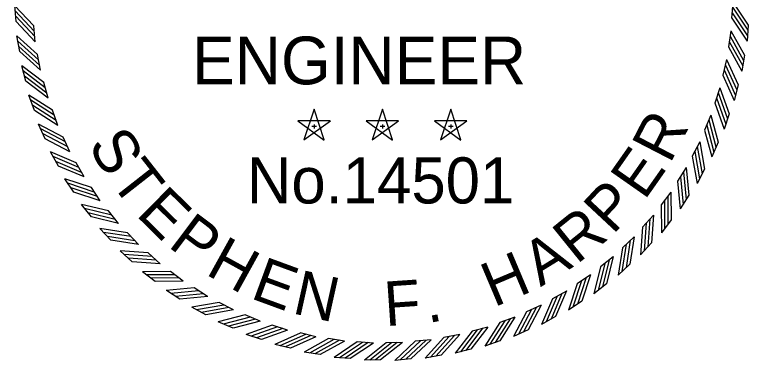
# Model space of a CAD drawing. Extents: x -129 to 14744569, y -102 to 1829048.
# Drawn here: x -104.853 to -102.792, y -100.653 to -99.681 of the extents above; entities that cross this region are included whole.
import ezdxf

# ---------------------------------------------------------------- set-up
doc = ezdxf.new("R2010")
doc.units = 0
doc.layers.add('STAMP', color=7, linetype='Continuous')

msp = doc.modelspace()

# ---------------------------------------------------------------- linework, layer by layer
at = {"layer": 'STAMP'}
for p, q in [((-104.8484, -99.6998), (-104.8525, -99.6547)), ((-102.8353, -99.6452), (-102.8387, -99.6904)), ((-104.7948, -99.7568), (-104.7989, -99.7117)), ((-102.7919, -99.7103), (-102.7952, -99.7554)), ((-102.8408, -99.7264), (-102.8478, -99.7712)), ((-104.8383, -99.7845), (-104.8461, -99.7399)), ((-104.7801, -99.8369), (-104.788, -99.7922)), ((-102.8028, -99.7948), (-102.8099, -99.8395)), ((-102.8529, -99.8068), (-102.8637, -99.8509)), ((-104.8212, -99.868), (-104.8327, -99.8243)), ((-104.7589, -99.9155), (-104.7705, -99.8716)), ((-102.8208, -99.8782), (-102.8315, -99.9222)), ((-102.8717, -99.886), (-102.886, -99.9291)), ((-104.7973, -99.9499), (-104.8124, -99.9072)), ((-104.7313, -99.992), (-104.7464, -99.9493)), ((-104.0117, -99.9462), (-104.04, -100.033)), ((-103.9835, -100.033), (-104.0116, -99.9461)), ((-103.8198, -99.9462), (-103.8481, -100.033)), ((-103.7916, -100.033), (-103.8197, -99.9461)), ((-103.6279, -99.9462), (-103.6562, -100.033)), ((-103.5997, -100.033), (-103.6278, -99.9461)), ((-102.8969, -99.9634), (-102.9147, -100.0051)), ((-102.8455, -99.9598), (-102.8598, -100.0027)), ((-103.966, -99.9794), (-104.0574, -99.9793)), ((-104.0573, -99.9794), (-103.9835, -100.0331)), ((-104.0399, -100.033), (-103.9659, -99.9794)), ((-103.7741, -99.9794), (-103.8655, -99.9793)), ((-103.8654, -99.9794), (-103.7916, -100.0331)), ((-103.848, -100.033), (-103.774, -99.9794)), ((-103.5822, -99.9794), (-103.6736, -99.9793)), ((-103.6735, -99.9794), (-103.5997, -100.0331)), ((-103.6561, -100.033), (-103.5821, -99.9794)), ((-104.7667, -100.0295), (-104.7852, -99.9882)), ((-104.0182, -99.9939), (-104.0046, -99.9939)), ((-104.0116, -99.9891), (-104.0116, -100.0005)), ((-103.8263, -99.9939), (-103.8127, -99.9939)), ((-103.8197, -99.9891), (-103.8197, -100.0005)), ((-103.6344, -99.9939), (-103.6208, -99.9939)), ((-103.6278, -99.9891), (-103.6278, -100.0005)), ((-104.6975, -100.066), (-104.716, -100.0247)), ((-102.9284, -100.0384), (-102.9496, -100.0785)), ((-102.8769, -100.0391), (-102.8947, -100.0807)), ((-104.7296, -100.1063), (-104.7515, -100.0667)), ((-104.6576, -100.137), (-104.6796, -100.0973)), ((-102.966, -100.1106), (-102.9905, -100.1488)), ((-102.9148, -100.1155), (-102.9359, -100.1555)), ((-104.6863, -100.1798), (-104.7114, -100.1421)), ((-104.612, -100.2044), (-104.6372, -100.1667)), ((-103.0095, -100.1794), (-103.037, -100.2155)), ((-102.9588, -100.1886), (-102.9832, -100.2267)), ((-104.6371, -100.2494), (-104.6653, -100.214)), ((-104.5611, -100.2679), (-104.5892, -100.2323)), ((-103.0585, -100.2444), (-103.0889, -100.2781)), ((-103.0087, -100.2577), (-103.0361, -100.2937)), ((-104.5824, -100.3148), (-104.6133, -100.2818)), ((-104.505, -100.3269), (-104.536, -100.2938)), ((-103.1126, -100.3052), (-103.1457, -100.3362)), ((-103.0641, -100.3225), (-103.0945, -100.3561)), ((-104.5224, -100.3754), (-104.5559, -100.345)), ((-104.4443, -100.381), (-104.4779, -100.3506)), ((-103.1717, -100.3612), (-103.2072, -100.3894)), ((-103.1247, -100.3825), (-103.1577, -100.4134)), ((-104.4576, -100.4308), (-104.4935, -100.4034)), ((-104.3793, -100.43), (-104.4153, -100.4025)), ((-103.2351, -100.4122), (-103.2728, -100.4373)), ((-103.1901, -100.4373), (-103.2255, -100.4654)), ((-104.3884, -100.4807), (-104.4265, -100.4563)), ((-104.3105, -100.4735), (-104.3487, -100.449)), ((-103.3025, -100.4578), (-103.3422, -100.4797)), ((-104.2383, -100.5111), (-104.2784, -100.4899)), ((-103.3735, -100.4976), (-103.4148, -100.5162)), ((-103.2598, -100.4865), (-103.2974, -100.5116)), ((-104.3154, -100.5247), (-104.3554, -100.5036)), ((-104.1633, -100.5426), (-104.205, -100.5248)), ((-103.4475, -100.5314), (-103.4902, -100.5466)), ((-103.3332, -100.5298), (-103.3728, -100.5517)), ((-104.239, -100.5626), (-104.2806, -100.5448)), ((-104.0859, -100.5678), (-104.1289, -100.5535)), ((-103.524, -100.5591), (-103.5679, -100.5706)), ((-104.1597, -100.594), (-104.2026, -100.5797)), ((-104.0067, -100.5866), (-104.0508, -100.5758)), ((-103.6026, -100.5803), (-103.6473, -100.5881)), ((-103.41, -100.5668), (-103.4513, -100.5854)), ((-103.9262, -100.5987), (-103.971, -100.5917)), ((-103.845, -100.6042), (-103.8903, -100.6008)), ((-103.7637, -100.6029), (-103.809, -100.6033)), ((-103.6827, -100.5949), (-103.7278, -100.5991)), ((-103.4896, -100.5974), (-103.5323, -100.6125)), ((-104.0781, -100.6187), (-104.122, -100.608)), ((-103.5715, -100.6213), (-103.6152, -100.6328)), ((-103.9947, -100.6367), (-104.0394, -100.6296)), ((-103.9101, -100.6477), (-103.9553, -100.6443)), ((-103.655, -100.6384), (-103.6996, -100.6463)), ((-103.8249, -100.6516), (-103.8702, -100.652)), ((-103.7397, -100.6485), (-103.7848, -100.6527))]:
    msp.add_line(p, q, dxfattribs=at)
for points in [[(-104.799, -99.7117), (-104.8526, -99.6547)], [(-102.8354, -99.6451), (-102.7919, -99.7102)], [(-104.7977, -99.7268), (-104.8513, -99.6697)], [(-102.8374, -99.6753), (-102.7939, -99.7404)], [(-102.8366, -99.6596), (-102.7931, -99.7247)], [(-104.7959, -99.7424), (-104.8495, -99.6853)], [(-102.8386, -99.6903), (-102.7951, -99.7554)], [(-104.7947, -99.7569), (-104.8483, -99.6998)], [(-102.8408, -99.7263), (-102.8029, -99.7948)], [(-104.788, -99.7923), (-104.8462, -99.7399)], [(-104.7855, -99.8072), (-104.8437, -99.7547)], [(-102.8453, -99.7563), (-102.8074, -99.8247)], [(-102.8432, -99.7407), (-102.8053, -99.8091)], [(-104.7825, -99.8226), (-104.8406, -99.7702)], [(-102.8478, -99.7711), (-102.8098, -99.8396)], [(-104.7801, -99.8369), (-104.8382, -99.7845)], [(-102.853, -99.8068), (-102.8208, -99.8781)], [(-104.7705, -99.8717), (-104.8327, -99.8242)], [(-104.7668, -99.8863), (-104.829, -99.8388)], [(-102.8599, -99.8362), (-102.8277, -99.9076)], [(-102.8565, -99.8209), (-102.8244, -99.8923)], [(-104.7624, -99.9014), (-104.8247, -99.8539)], [(-102.8636, -99.8509), (-102.8314, -99.9222)], [(-104.7589, -99.9155), (-104.8211, -99.8681)], [(-102.8764, -99.8997), (-102.8503, -99.9735)], [(-102.8717, -99.886), (-102.8455, -99.9597)], [(-104.7464, -99.9493), (-104.8124, -99.9072)], [(-104.7415, -99.9636), (-104.8075, -99.9214)], [(-102.8811, -99.9148), (-102.8549, -99.9885)], [(-104.736, -99.9783), (-104.8019, -99.9361)], [(-102.886, -99.929), (-102.8598, -100.0028)], [(-104.7312, -99.9921), (-104.7972, -99.9499)], [(-102.8969, -99.9634), (-102.8769, -100.039)], [(-102.9028, -99.9767), (-102.8828, -100.0524)], [(-104.7161, -100.0247), (-104.7853, -99.9882)], [(-104.71, -100.0385), (-104.7792, -100.002)], [(-102.9147, -100.0051), (-102.8947, -100.0808)], [(-102.9086, -99.9913), (-102.8886, -100.067)], [(-104.7032, -100.0527), (-104.7725, -100.0162)], [(-104.6974, -100.0661), (-104.7666, -100.0295)], [(-102.9284, -100.0384), (-102.9148, -100.1155)], [(-104.6796, -100.0974), (-104.7516, -100.0667)], [(-102.9424, -100.0652), (-102.9287, -100.1423)], [(-102.9354, -100.0512), (-102.9217, -100.1283)], [(-104.6724, -100.1106), (-104.7444, -100.0799)], [(-102.9496, -100.0785), (-102.9359, -100.1556)], [(-104.6645, -100.1242), (-104.7365, -100.0935)], [(-104.6575, -100.137), (-104.7295, -100.1063)], [(-102.974, -100.1227), (-102.9668, -100.2007)], [(-102.966, -100.1105), (-102.9588, -100.1885)], [(-104.6372, -100.1668), (-104.7115, -100.1421)], [(-102.9904, -100.1488), (-102.9832, -100.2267)], [(-102.9822, -100.1362), (-102.9749, -100.2141)], [(-104.6289, -100.1794), (-104.7032, -100.1547)], [(-104.6199, -100.1923), (-104.6942, -100.1676)], [(-104.612, -100.2044), (-104.6863, -100.1798)], [(-103.0184, -100.1909), (-103.0176, -100.2691)], [(-103.0095, -100.1794), (-103.0087, -100.2576)], [(-103.0277, -100.2036), (-103.0269, -100.2818)], [(-104.5892, -100.2324), (-104.6653, -100.214)], [(-104.58, -100.2443), (-104.656, -100.2258)], [(-103.0369, -100.2154), (-103.0361, -100.2937)], [(-104.5699, -100.2564), (-104.646, -100.2379)], [(-104.561, -100.2679), (-104.6371, -100.2494)], [(-103.0585, -100.2444), (-103.0641, -100.3224)], [(-103.0786, -100.267), (-103.0843, -100.345)], [(-103.0683, -100.2551), (-103.074, -100.3331)], [(-104.536, -100.2938), (-104.6134, -100.2818)], [(-104.5258, -100.3049), (-104.6031, -100.2928)], [(-103.0888, -100.2781), (-103.0945, -100.3561)], [(-104.5148, -100.3162), (-104.5921, -100.3041)], [(-104.5049, -100.3269), (-104.5823, -100.3148)], [(-103.1233, -100.3149), (-103.1354, -100.3923)], [(-103.1126, -100.3051), (-103.1247, -100.3824)], [(-103.1346, -100.326), (-103.1467, -100.4033)], [(-104.4779, -100.3507), (-104.556, -100.345)], [(-104.4668, -100.3609), (-104.5449, -100.3552)], [(-103.1457, -100.3362), (-103.1578, -100.4135)], [(-104.4549, -100.3712), (-104.533, -100.3655)], [(-104.4442, -100.381), (-104.5223, -100.3754)], [(-103.1831, -100.3701), (-103.2016, -100.4462)], [(-103.1716, -100.3611), (-103.1901, -100.4372)], [(-103.2071, -100.3894), (-103.2256, -100.4654)], [(-103.1952, -100.3801), (-103.2137, -100.4562)], [(-104.4153, -100.4026), (-104.4936, -100.4034)], [(-104.4034, -100.4118), (-104.4817, -100.4126)], [(-103.2351, -100.4121), (-103.2597, -100.4864)], [(-104.3907, -100.4211), (-104.469, -100.4219)], [(-104.3792, -100.43), (-104.4575, -100.4308)], [(-103.2728, -100.4373), (-103.2974, -100.5116)], [(-103.2601, -100.4291), (-103.2848, -100.5034)], [(-103.2473, -100.4201), (-103.2719, -100.4944)], [(-104.3486, -100.4491), (-104.4266, -100.4563)], [(-104.336, -100.4573), (-104.414, -100.4646)], [(-103.3025, -100.4577), (-103.3332, -100.5297)], [(-104.3226, -100.4655), (-104.4005, -100.4728)], [(-104.3104, -100.4735), (-104.3883, -100.4807)], [(-103.3421, -100.4797), (-103.3728, -100.5517)], [(-103.3289, -100.4725), (-103.3596, -100.5445)], [(-103.3153, -100.4646), (-103.346, -100.5366)], [(-104.2783, -100.4899), (-104.3554, -100.5036)], [(-104.2651, -100.4971), (-104.3422, -100.5108)], [(-103.3734, -100.4975), (-103.41, -100.5668)], [(-104.251, -100.5041), (-104.3281, -100.5178)], [(-104.2382, -100.5111), (-104.3153, -100.5247)], [(-103.4148, -100.5162), (-103.4513, -100.5854)], [(-103.401, -100.5101), (-103.4375, -100.5794)], [(-103.3868, -100.5034), (-103.4233, -100.5726)], [(-104.2049, -100.5248), (-104.2806, -100.5448)], [(-104.1911, -100.5309), (-104.2668, -100.5509)], [(-104.1765, -100.5367), (-104.2522, -100.5567)], [(-103.4759, -100.5417), (-103.5181, -100.6076)], [(-103.4612, -100.5361), (-103.5034, -100.6021)], [(-103.4475, -100.5314), (-103.4896, -100.5974)], [(-104.1632, -100.5426), (-104.2389, -100.5626)], [(-104.1289, -100.5535), (-104.2027, -100.5797)], [(-104.1146, -100.5584), (-104.1884, -100.5846)], [(-103.524, -100.559), (-103.5714, -100.6213)], [(-103.4902, -100.5466), (-103.5323, -100.6125)], [(-104.0996, -100.5631), (-104.1734, -100.5892)], [(-104.0858, -100.5678), (-104.1596, -100.594)], [(-104.0507, -100.5759), (-104.1221, -100.6081)], [(-104.0361, -100.5796), (-104.1075, -100.6118)], [(-104.0208, -100.583), (-104.0921, -100.6151)], [(-103.6169, -100.5826), (-103.6694, -100.6407)], [(-103.6026, -100.5802), (-103.655, -100.6384)], [(-103.5678, -100.5706), (-103.6153, -100.6329)], [(-103.5532, -100.5669), (-103.6007, -100.6292)], [(-103.5381, -100.5626), (-103.5856, -100.6248)], [(-104.0066, -100.5865), (-104.078, -100.6187)], [(-103.971, -100.5917), (-104.0394, -100.6297)], [(-103.9561, -100.5942), (-104.0246, -100.6321)], [(-103.9405, -100.5963), (-104.009, -100.6342)], [(-103.9262, -100.5987), (-103.9946, -100.6366)], [(-103.8902, -100.6009), (-103.9553, -100.6444)], [(-103.8752, -100.6021), (-103.9403, -100.6456)], [(-103.8595, -100.6029), (-103.9246, -100.6464)], [(-103.8089, -100.6034), (-103.8702, -100.6521)], [(-103.7939, -100.6034), (-103.8552, -100.6521)], [(-103.7782, -100.6029), (-103.8394, -100.6516)], [(-103.7636, -100.6029), (-103.8249, -100.6516)], [(-103.7278, -100.5991), (-103.7848, -100.6527)], [(-103.7127, -100.5979), (-103.7698, -100.6515)], [(-103.6971, -100.5961), (-103.7542, -100.6497)], [(-103.6826, -100.5949), (-103.7397, -100.6485)], [(-103.6472, -100.5882), (-103.6996, -100.6463)], [(-103.6323, -100.5857), (-103.6848, -100.6438)], [(-103.845, -100.6041), (-103.9101, -100.6476)]]:
    msp.add_lwpolyline(points, dxfattribs=at)

# ---------------------------------------------------------------- texts
for s, height, p in [('ENGINEER', 0.13433, (-104.3541, -99.8766)), ('No.14501', 0.12953, (-104.2005, -100.2115))]:
    msp.add_text(s, height=height, dxfattribs=at).set_placement(p)
for s, rotation, p in [('R', 62.6418, (-103.0123, -100.1024)), ('S', 300.7985, (-104.6488, -100.0475)), ('E', 54.981, (-103.0838, -100.2052)), ('T', 308.0945, (-104.5878, -100.1499)), ('E', 315.3905, (-104.5142, -100.2437)), ('P', 46.9554, (-103.1727, -100.3016)), ('R', 38.9298, (-103.2741, -100.3846)), ('P', 323.0513, (-104.4248, -100.3313)), ('H', 331.0769, (-104.3195, -100.4094)), ('A', 31.6338, (-103.3756, -100.4472)), ('H', 22.8786, (-103.5067, -100.5044)), ('E', 339.8321, (-104.1935, -100.477)), ('N', 347.4929, (-104.0759, -100.5198)), ('F', 3.9089, (-103.8109, -100.5567)), ('.', 11.205, (-103.692, -100.5486))]:
    msp.add_text(s, height=0.125, rotation=rotation, dxfattribs=at).set_placement(p)

doc.saveas('drawing.dxf')
